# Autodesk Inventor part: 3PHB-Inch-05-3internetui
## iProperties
Created: 2010-11
Part Number: 3PHB-Inch-05-3internetui
Document SubType Name: Modeling
Designer: Darius
Author: Darius
Translation Standard: STEP AP203
File Name: 3PHB-Inch-05-3.STEP
Preprocessor: SolidWorks 2003240
Postprocessor: Build: 272, Release: 10 SP3a - Date: Thu 12/15/2005
Sent Units: MILLIMETERS
Uncertainty: 1e-05
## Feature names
1. Base1
